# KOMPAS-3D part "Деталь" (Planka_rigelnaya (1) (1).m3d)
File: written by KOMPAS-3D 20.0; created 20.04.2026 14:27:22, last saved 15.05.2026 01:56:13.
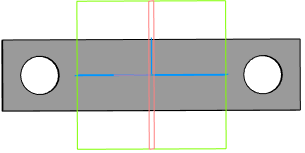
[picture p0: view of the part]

Document properties: Автор: TMK; Полное имя файла: E:\test_kompas\all_v18\Planka_rigelnaya (1) (1).m3d; Организация: TMK

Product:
- Part/product: Деталь
    Масса: 0.134151
  - Body: Тело 1

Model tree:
1. Эскиз:1
2. Элемент выдавливания:1
     Расстояние 2 = 8
3. Эскиз:2
4. Элемент выдавливания:2
     Расстояние 2 = 10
